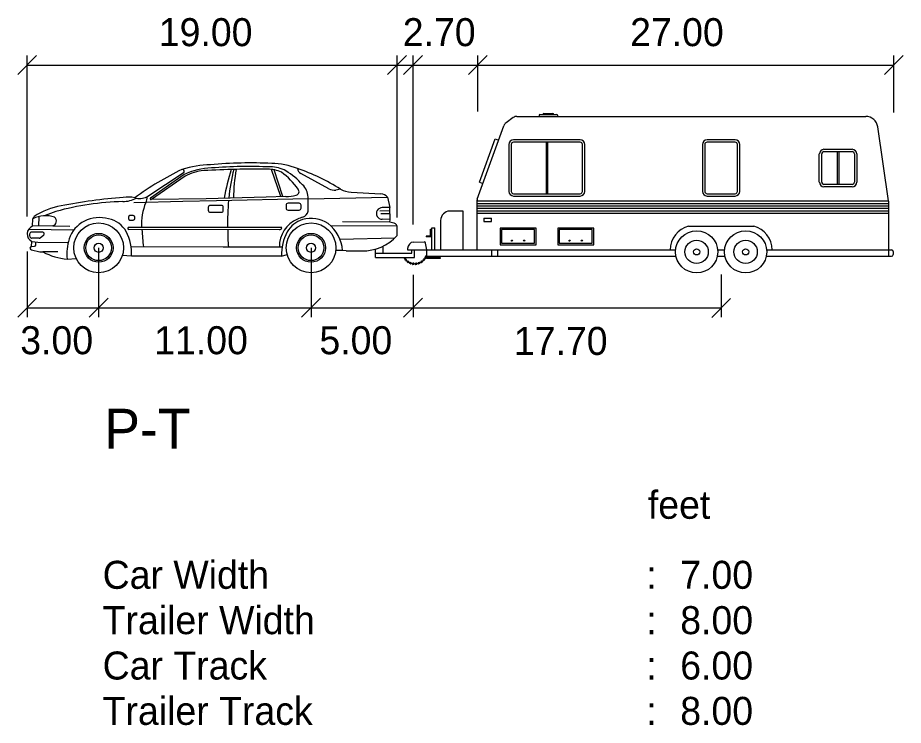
# Model space of a CAD drawing. Extents: x 2297881 to 2300600, y 559917 to 564426.
# Drawn here: x 2299107.93 to 2299149.45, y 562721.47 to 562754.62 of the extents above; entities that cross this region are included whole.
import ezdxf

# ---------------------------------------------------------------- set-up
doc = ezdxf.new("R2010")
doc.units = 0
doc.layers.add('DR_X_Elev_Flow', color=7, linetype='Continuous')

msp = doc.modelspace()

# ---------------------------------------------------------------- linework, layer by layer
at = {"layer": 'DR_X_Elev_Flow'}
for p, q in [((2299108.812, 562752.842), (2299107.926, 562751.957)), ((2299108.369, 562745.307), (2299108.369, 562752.842)), ((2299126.157, 562752.842), (2299125.271, 562751.957)), ((2299125.714, 562745.255), (2299125.714, 562752.842)), ((2299126.905, 562752.842), (2299126.019, 562751.957)), ((2299126.462, 562744.925), (2299126.462, 562752.842)), ((2299129.941, 562752.842), (2299129.055, 562751.957)), ((2299129.498, 562750.218), (2299129.498, 562752.842)), ((2299149.446, 562752.842), (2299148.561, 562751.957)), ((2299149.004, 562750.183), (2299149.004, 562752.842)), ((2299108.369, 562752.4), (2299149.004, 562752.4)), ((2299131.329, 562749.996), (2299147.683, 562749.996)), ((2299132.374, 562750.054), (2299132.374, 562749.996)), ((2299132.402, 562750.083), (2299133.207, 562750.083)), ((2299132.596, 562750.136), (2299133.013, 562750.136)), ((2299133.236, 562750.054), (2299133.236, 562749.996)), ((2299131.161, 562749.942), (2299130.821, 562749.696)), ((2299129.474, 562746.124), (2299130.716, 562749.553)), ((2299148.752, 562746.043), (2299148.252, 562749.504)), ((2299129.573, 562746.908), (2299130.311, 562748.945)), ((2299130.311, 562748.945), (2299130.474, 562748.886)), ((2299134.297, 562748.894), (2299131.174, 562748.894)), ((2299134.297, 562748.785), (2299131.174, 562748.785)), ((2299132.699, 562748.785), (2299132.699, 562746.374)), ((2299132.771, 562748.785), (2299132.771, 562746.374)), ((2299141.565, 562748.894), (2299140.249, 562748.894)), ((2299141.565, 562748.785), (2299140.249, 562748.785)), ((2299130.955, 562748.676), (2299130.955, 562746.483)), ((2299131.064, 562748.676), (2299131.064, 562746.483)), ((2299134.406, 562746.483), (2299134.406, 562748.676)), ((2299134.516, 562746.483), (2299134.516, 562748.676)), ((2299140.03, 562748.676), (2299140.03, 562746.483)), ((2299140.14, 562748.676), (2299140.14, 562746.483)), ((2299141.674, 562746.483), (2299141.674, 562748.676)), ((2299141.784, 562746.483), (2299141.784, 562748.676)), ((2299145.729, 562748.452), (2299147.045, 562748.452)), ((2299145.729, 562748.343), (2299147.045, 562748.343)), ((2299146.351, 562748.343), (2299146.351, 562746.808)), ((2299146.423, 562748.343), (2299146.423, 562746.808)), ((2299145.51, 562746.918), (2299145.51, 562748.234)), ((2299145.62, 562746.918), (2299145.62, 562748.234)), ((2299147.154, 562748.234), (2299147.154, 562746.918)), ((2299147.264, 562748.234), (2299147.264, 562746.918)), ((2299120.261, 562746.24), (2299119.831, 562747.51)), ((2299113.982, 562746.228), (2299115.732, 562747.378)), ((2299115.724, 562747.279), (2299114.155, 562746.167)), ((2299115.772, 562747.19), (2299114.192, 562746.1)), ((2299120.364, 562746.244), (2299119.945, 562747.492)), ((2299122.515, 562746.604), (2299121.198, 562747.32)), ((2299129.573, 562746.908), (2299129.737, 562746.849)), ((2299147.045, 562746.808), (2299145.729, 562746.808)), ((2299147.045, 562746.699), (2299145.729, 562746.699)), ((2299123.061, 562746.584), (2299122.843, 562746.543)), ((2299123.559, 562746.447), (2299124.951, 562746.359)), ((2299131.174, 562746.374), (2299134.297, 562746.374)), ((2299131.174, 562746.264), (2299134.297, 562746.264)), ((2299140.249, 562746.374), (2299141.565, 562746.374)), ((2299140.249, 562746.264), (2299141.565, 562746.264)), ((2299115.673, 562746.004), (2299113.363, 562745.949)), ((2299116.765, 562746.14), (2299114.177, 562746.1)), ((2299117.245, 562746.044), (2299115.673, 562746.004)), ((2299119.572, 562746.215), (2299116.765, 562746.14)), ((2299121.545, 562746.137), (2299117.245, 562746.044)), ((2299120.493, 562746.249), (2299119.572, 562746.215)), ((2299121.118, 562745.926), (2299120.599, 562745.926)), ((2299121.537, 562745.997), (2299121.544, 562746.215)), ((2299121.537, 562745.557), (2299121.537, 562745.997)), ((2299121.545, 562746.137), (2299125.265, 562746.218)), ((2299125.265, 562746.218), (2299125.38, 562745.732)), ((2299129.46, 562746.033), (2299148.753, 562746.033)), ((2299129.46, 562746.033), (2299129.46, 562743.739)), ((2299129.46, 562745.918), (2299148.753, 562745.918)), ((2299148.753, 562746.023), (2299148.753, 562743.447)), ((2299109.72, 562745.542), (2299109.212, 562745.344)), ((2299116.863, 562745.732), (2299116.863, 562745.595)), ((2299117.474, 562745.824), (2299116.955, 562745.824)), ((2299116.955, 562745.503), (2299117.474, 562745.503)), ((2299117.566, 562745.595), (2299117.566, 562745.732)), ((2299120.507, 562745.834), (2299120.507, 562745.698)), ((2299120.599, 562745.605), (2299121.118, 562745.605)), ((2299121.21, 562745.698), (2299121.21, 562745.834)), ((2299125.381, 562745.564), (2299124.908, 562745.561)), ((2299125.382, 562745.422), (2299124.947, 562745.425)), ((2299125.38, 562745.732), (2299125.02, 562745.719)), ((2299125.383, 562745.158), (2299125.38, 562745.732)), ((2299128.81, 562745.557), (2299128.187, 562745.557)), ((2299128.81, 562743.739), (2299128.81, 562745.557)), ((2299129.46, 562745.803), (2299148.753, 562745.803)), ((2299129.46, 562745.688), (2299148.753, 562745.688)), ((2299129.46, 562745.573), (2299148.753, 562745.573)), ((2299129.46, 562745.458), (2299148.753, 562745.458)), ((2299108.62, 562744.849), (2299108.634, 562745.199)), ((2299108.634, 562745.199), (2299108.698, 562745.299)), ((2299108.913, 562744.856), (2299108.938, 562745.311)), ((2299113.114, 562745.274), (2299113.114, 562745.21)), ((2299113.347, 562745.348), (2299113.188, 562745.348)), ((2299113.188, 562745.136), (2299113.347, 562745.136)), ((2299113.421, 562745.21), (2299113.421, 562745.274)), ((2299125.38, 562745.039), (2299123.154, 562745.049)), ((2299125.383, 562745.158), (2299125.017, 562745.174)), ((2299125.38, 562745.039), (2299125.383, 562745.158)), ((2299125.504, 562745.005), (2299125.38, 562745.039)), ((2299127.756, 562745.125), (2299127.756, 562743.739)), ((2299129.782, 562745.231), (2299130.135, 562745.231)), ((2299129.782, 562745.231), (2299129.782, 562745.073)), ((2299129.782, 562745.073), (2299130.135, 562745.073)), ((2299130.135, 562745.073), (2299130.135, 562745.231)), ((2299110.556, 562744.67), (2299108.427, 562744.69)), ((2299109.57, 562744.871), (2299108.62, 562744.849)), ((2299109.57, 562744.871), (2299110.37, 562744.849)), ((2299120.313, 562744.787), (2299113.104, 562744.79)), ((2299120.197, 562744.685), (2299113.139, 562744.693)), ((2299125.714, 562744.854), (2299122.612, 562744.868)), ((2299125.714, 562744.413), (2299125.714, 562744.854)), ((2299127.281, 562744.706), (2299127.337, 562744.706)), ((2299127.281, 562744.355), (2299127.281, 562744.706)), ((2299127.315, 562744.355), (2299127.315, 562744.706)), ((2299127.315, 562744.615), (2299127.337, 562744.615)), ((2299127.337, 562743.739), (2299127.337, 562744.771)), ((2299127.337, 562744.771), (2299127.48, 562744.771)), ((2299127.48, 562743.739), (2299127.48, 562744.771)), ((2299132.227, 562744.762), (2299130.54, 562744.762)), ((2299130.54, 562744.762), (2299130.54, 562743.978)), ((2299132.155, 562744.69), (2299130.611, 562744.69)), ((2299130.611, 562744.69), (2299130.611, 562744.05)), ((2299132.155, 562744.05), (2299132.155, 562744.69)), ((2299132.227, 562743.978), (2299132.227, 562744.762)), ((2299133.244, 562744.762), (2299133.244, 562743.978)), ((2299134.931, 562744.762), (2299133.244, 562744.762)), ((2299133.316, 562744.69), (2299133.316, 562744.05)), ((2299134.859, 562744.69), (2299133.316, 562744.69)), ((2299134.859, 562744.05), (2299134.859, 562744.69)), ((2299134.931, 562743.978), (2299134.931, 562744.762)), ((2299139.379, 562744.851), (2299142.435, 562744.851)), ((2299109.101, 562744.572), (2299108.575, 562744.572)), ((2299108.933, 562744.287), (2299108.59, 562744.287)), ((2299108.979, 562744.303), (2299109.148, 562744.442)), ((2299125.601, 562744.297), (2299123.031, 562744.231)), ((2299127.078, 562744.39), (2299127.078, 562744.355)), ((2299127.281, 562744.39), (2299127.078, 562744.39)), ((2299127.315, 562744.355), (2299127.078, 562744.355)), ((2299108.566, 562743.897), (2299108.583, 562744.14)), ((2299108.566, 562743.897), (2299108.709, 562743.912)), ((2299108.583, 562744.14), (2299108.873, 562744.097)), ((2299108.775, 562743.983), (2299108.779, 562744.111)), ((2299108.873, 562744.097), (2299110.259, 562744.09)), ((2299111.721, 562743.839), (2299111.721, 562740.59)), ((2299117.559, 562743.873), (2299113.244, 562743.882)), ((2299120.323, 562743.873), (2299117.559, 562743.873)), ((2299121.68, 562743.839), (2299121.68, 562740.59)), ((2299124.7, 562743.39), (2299124.7, 562743.778)), ((2299125.056, 562743.59), (2299125.056, 562743.915)), ((2299126.209, 562743.807), (2299126.209, 562743.739)), ((2299126.492, 562744.107), (2299126.979, 562744.122)), ((2299127.109, 562743.739), (2299127.052, 562744.062)), ((2299130.54, 562743.978), (2299132.227, 562743.978)), ((2299130.611, 562744.05), (2299132.155, 562744.05)), ((2299133.244, 562743.978), (2299134.931, 562743.978)), ((2299133.316, 562744.05), (2299134.859, 562744.05)), ((2299108.369, 562743.666), (2299108.369, 562740.59)), ((2299109.802, 562743.654), (2299109.109, 562743.647)), ((2299113.26, 562743.445), (2299112.83, 562743.48)), ((2299120.298, 562743.45), (2299113.26, 562743.445)), ((2299120.298, 562743.45), (2299120.558, 562743.523)), ((2299123.113, 562743.714), (2299122.839, 562743.717)), ((2299123.32, 562743.693), (2299123.113, 562743.714)), ((2299123.32, 562743.693), (2299124.06, 562743.693)), ((2299124.7, 562743.59), (2299126.399, 562743.59)), ((2299124.7, 562743.39), (2299126.525, 562743.39)), ((2299126.03, 562743.365), (2299126.015, 562743.39)), ((2299126.099, 562743.296), (2299126.057, 562743.37)), ((2299126.067, 562743.36), (2299126.061, 562743.356)), ((2299126.209, 562743.739), (2299138.521, 562743.739)), ((2299126.399, 562743.59), (2299126.399, 562743.739)), ((2299126.525, 562743.39), (2299126.525, 562743.739)), ((2299127.033, 562743.361), (2299126.981, 562743.294)), ((2299127.025, 562743.413), (2299127.009, 562743.377)), ((2299127.086, 562743.488), (2299127.052, 562743.41)), ((2299127.055, 562743.425), (2299127.061, 562743.422)), ((2299127.073, 562743.392), (2299127.058, 562743.356)), ((2299127.089, 562743.739), (2299127.089, 562743.447)), ((2299127.089, 562743.447), (2299130.42, 562743.447)), ((2299127.089, 562743.378), (2299127.089, 562743.343)), ((2299127.728, 562743.378), (2299127.089, 562743.378)), ((2299127.337, 562743.378), (2299127.337, 562743.447)), ((2299127.48, 562743.378), (2299127.48, 562743.447)), ((2299127.728, 562743.378), (2299127.728, 562743.343)), ((2299130.133, 562743.739), (2299130.133, 562743.447)), ((2299130.42, 562743.739), (2299130.42, 562743.447)), ((2299130.42, 562743.447), (2299138.79, 562743.447)), ((2299138.521, 562743.739), (2299138.774, 562743.739)), ((2299140.726, 562743.447), (2299141.088, 562743.447)), ((2299140.743, 562743.739), (2299141.072, 562743.739)), ((2299143.024, 562743.447), (2299148.753, 562743.447)), ((2299143.041, 562743.739), (2299143.293, 562743.739)), ((2299143.293, 562743.739), (2299148.9, 562743.739)), ((2299148.753, 562743.447), (2299148.9, 562743.447)), ((2299148.972, 562743.667), (2299148.972, 562743.519)), ((2299110.246, 562743.307), (2299110.669, 562743.337)), ((2299126.112, 562743.248), (2299126.085, 562743.276)), ((2299126.09, 562743.313), (2299126.086, 562743.309)), ((2299126.15, 562743.284), (2299126.123, 562743.313)), ((2299126.196, 562743.198), (2299126.137, 562743.26)), ((2299126.149, 562743.252), (2299126.144, 562743.247)), ((2299126.184, 562743.213), (2299126.18, 562743.207)), ((2299126.22, 562743.154), (2299126.187, 562743.175)), ((2299126.249, 562743.199), (2299126.215, 562743.22)), ((2299126.314, 562743.127), (2299126.242, 562743.172)), ((2299126.256, 562743.167), (2299126.252, 562743.161)), ((2299126.298, 562743.137), (2299126.296, 562743.131)), ((2299126.348, 562743.09), (2299126.311, 562743.102)), ((2299126.365, 562743.14), (2299126.327, 562743.152)), ((2299126.446, 562743.086), (2299126.365, 562743.112)), ((2299126.379, 562743.111), (2299126.377, 562743.105)), ((2299126.428, 562743.093), (2299126.428, 562743.086)), ((2299126.488, 562743.059), (2299126.449, 562743.061)), ((2299126.492, 562743.111), (2299126.453, 562743.114)), ((2299126.583, 562743.078), (2299126.498, 562743.084)), ((2299126.513, 562743.087), (2299126.513, 562743.08)), ((2299126.565, 562743.081), (2299126.566, 562743.074)), ((2299126.622, 562743.114), (2299126.583, 562743.107)), ((2299126.631, 562743.062), (2299126.593, 562743.055)), ((2299126.719, 562743.105), (2299126.635, 562743.09)), ((2299126.649, 562743.096), (2299126.65, 562743.089)), ((2299126.7, 562743.102), (2299126.703, 562743.096)), ((2299126.748, 562743.149), (2299126.712, 562743.133)), ((2299126.769, 562743.101), (2299126.733, 562743.085)), ((2299126.844, 562743.163), (2299126.766, 562743.128)), ((2299126.778, 562743.137), (2299126.781, 562743.131)), ((2299126.826, 562743.156), (2299126.83, 562743.151)), ((2299126.861, 562743.213), (2299126.83, 562743.189)), ((2299126.894, 562743.172), (2299126.863, 562743.147)), ((2299126.951, 562743.25), (2299126.884, 562743.198)), ((2299126.893, 562743.209), (2299126.897, 562743.204)), ((2299126.955, 562743.303), (2299126.931, 562743.272)), ((2299126.935, 562743.24), (2299126.941, 562743.235)), ((2299126.997, 562743.271), (2299126.973, 562743.24)), ((2299126.987, 562743.307), (2299126.993, 562743.303)), ((2299127.021, 562743.347), (2299127.027, 562743.344)), ((2299127.728, 562743.343), (2299127.089, 562743.343)), ((2299126.462, 562742.57), (2299126.462, 562740.59)), ((2299140.907, 562742.592), (2299140.907, 562740.59)), ((2299108.812, 562741.476), (2299107.926, 562740.59)), ((2299112.164, 562741.476), (2299111.278, 562740.59)), ((2299122.123, 562741.476), (2299121.237, 562740.59)), ((2299126.905, 562741.476), (2299126.019, 562740.59)), ((2299141.35, 562741.459), (2299140.464, 562740.573)), ((2299108.369, 562741.033), (2299140.907, 562741.033))]:
    msp.add_line(p, q, dxfattribs=at)
for centre, radius in [((2299111.721, 562743.839), 1.166), ((2299121.68, 562743.839), 1.166), ((2299139.758, 562743.648), 0.989), ((2299142.056, 562743.648), 0.989), ((2299111.721, 562743.839), 0.677), ((2299111.721, 562743.839), 0.603), ((2299121.68, 562743.839), 0.677), ((2299121.68, 562743.839), 0.603), ((2299131.096, 562744.174), 0.0256), ((2299131.67, 562744.174), 0.0256), ((2299133.8, 562744.174), 0.0256), ((2299134.375, 562744.174), 0.0256), ((2299139.758, 562743.648), 0.547), ((2299142.056, 562743.648), 0.547), ((2299111.719, 562743.839), 0.214), ((2299121.678, 562743.839), 0.214), ((2299139.758, 562743.648), 0.144), ((2299142.056, 562743.648), 0.144)]:
    msp.add_circle(centre, radius, dxfattribs=at)
for centre, radius, start, end in [((2299131.329, 562749.709), 0.287, 90, 125.8387), ((2299132.402, 562750.054), 0.0287, 90, 180), ((2299132.609, 562750.081), 0.0567, 103.353, 178.0683), ((2299133, 562750.081), 0.0567, 1.9317, 76.647), ((2299133.207, 562750.054), 0.0287, 0, 90), ((2299147.683, 562749.421), 0.575, 8.2273, 90), ((2299130.989, 562749.463), 0.287, 125.8387, 161.6774), ((2299131.174, 562748.676), 0.218, 90, 180), ((2299131.174, 562748.676), 0.109, 90, 180), ((2299134.297, 562748.676), 0.218, 360, 90), ((2299134.297, 562748.676), 0.109, 360, 90), ((2299140.249, 562748.676), 0.218, 90, 180), ((2299140.249, 562748.676), 0.109, 90, 180), ((2299141.565, 562748.676), 0.218, 360, 90), ((2299141.565, 562748.676), 0.109, 360, 90), ((2299145.729, 562748.234), 0.218, 90, 180), ((2299145.729, 562748.234), 0.109, 90, 180), ((2299147.045, 562748.234), 0.218, 360, 90), ((2299147.045, 562748.234), 0.109, 360, 90), ((2299122.201, 562734.033), 14.995, 115.9971, 125.8595), ((2299117.126, 562742.542), 5.189, 91.7728, 106.767), ((2299115.641, 562747.413), 0.098, 338.7512, 97.138), ((2299117.129, 562744.166), 3.414, 92.0559, 114.2845), ((2299119.064, 562702.476), 45.045, 89.2591, 93.0743), ((2299118.855, 562726.648), 21.165, 87.3513, 95.1236), ((2299118.785, 562724.592), 23.056, 87.553, 94.4258), ((2299127.218, 562744.588), 9.735, 162.5527, 170.6899), ((2299125.966, 562745.415), 8.179, 165.1593, 174.7143), ((2299124.261, 562746.251), 6.214, 168.2882, 180.7049), ((2299119.686, 562746.184), 1.334, 63.154, 91.6788), ((2299119.786, 562746.151), 1.476, 61.0673, 90.63), ((2299119.814, 562744.515), 3.275, 67.9907, 89.6559), ((2299118.013, 562738.644), 9.408, 57.553, 71.2258), ((2299121.302, 562747.559), 0.261, 181.6185, 246.5782), ((2299116.798, 562745.39), 2.072, 94.1205, 119.6618), ((2299118.523, 562744.837), 3.091, 34.3906, 55.159), ((2299118.666, 562744.449), 3.51, 41.9269, 58.5069), ((2299120.668, 562746.164), 0.877, 3.3428, 45.9853), ((2299145.729, 562746.918), 0.218, 180, 270), ((2299145.729, 562746.918), 0.109, 180, 270), ((2299147.045, 562746.918), 0.218, 270, 0), ((2299147.045, 562746.918), 0.109, 270, 0), ((2299120.575, 562747.747), 1.5, 266.8503, 285.8201), ((2299120.944, 562746.47), 0.171, 283.5223, 41.2666), ((2299122.791, 562747.174), 0.634, 244.1451, 274.6321), ((2299123.596, 562747.561), 1.114, 241.2884, 268.0918), ((2299124.958, 562745.955), 0.404, 40.5709, 90.998), ((2299131.174, 562746.483), 0.218, 180, 270), ((2299131.174, 562746.483), 0.109, 180, 270), ((2299134.297, 562746.483), 0.218, 270, 0), ((2299134.297, 562746.483), 0.109, 270, 0), ((2299140.249, 562746.483), 0.218, 180, 270), ((2299140.249, 562746.483), 0.109, 180, 270), ((2299141.565, 562746.483), 0.109, 270, 0), ((2299141.565, 562746.483), 0.218, 270, 0), ((2299113.23, 562732.654), 13.358, 91.634, 105.2352), ((2299115.018, 562719.291), 26.993, 94.5482, 100.7946), ((2299112.842, 562747.436), 1.43, 270.2883, 297.1222), ((2299113.11, 562744.649), 1.567, 78.6761, 98.514), ((2299113.651, 562746.845), 0.7, 250.4981, 298.1814), ((2299116.518, 562744.918), 2.79, 158.0053, 182.6323), ((2299113.687, 562746.146), 0.306, 323.1539, 15.5477), ((2299114.176, 562746.137), 0.0368, 125.3064, 270.8889), ((2299131.873, 562744.889), 14.111, 175.2533, 180.4142), ((2299120.599, 562745.834), 0.0921, 90, 180), ((2299121.118, 562745.834), 0.0921, 0, 90), ((2299129.747, 562746.033), 0.287, 161.6774, 180), ((2299148.466, 562746.023), 0.287, 0, 3.965), ((2299110.553, 562742.504), 3.355, 100.1254, 123.5574), ((2299116.955, 562745.732), 0.0921, 90, 180), ((2299116.955, 562745.595), 0.0921, 180, 270), ((2299117.474, 562745.732), 0.0921, 0, 90), ((2299117.474, 562745.595), 0.0921, 270, 0), ((2299120.599, 562745.698), 0.0921, 180, 270), ((2299121.118, 562745.698), 0.0921, 270, 0), ((2299121.156, 562745.626), 0.387, 292.0027, 349.7344), ((2299125.017, 562745.447), 0.272, 89.4303, 269.8747), ((2299128.187, 562745.125), 0.431, 90, 180), ((2299109.228, 562744.056), 1.288, 70.5762, 117.4353), ((2299109.513, 562745.092), 0.229, 284.4681, 51.3236), ((2299111.665, 562743.85), 1.38, 116.4084, 163.0738), ((2299111.768, 562743.629), 1.623, 74.9346, 116.1868), ((2299111.961, 562744.019), 1.2, 28.748, 78.9995), ((2299113.188, 562745.274), 0.0736, 90, 180), ((2299113.188, 562745.21), 0.0736, 180, 270), ((2299113.347, 562745.274), 0.0736, 0, 90), ((2299113.347, 562745.21), 0.0736, 270, 360), ((2299121.555, 562743.92), 1.357, 112.0964, 181.968), ((2299121.669, 562743.931), 1.288, 107.4038, 149.7131), ((2299121.458, 562744.414), 0.869, 100.4094, 118.442), ((2299121.683, 562743.692), 1.521, 58.1254, 105.2223), ((2299108.758, 562744.486), 0.388, 110.8051, 243.2128), ((2299111.117, 562743.587), 2.147, 356.206, 28.0052), ((2299113.144, 562744.75), 0.0565, 134.529, 265.0873), ((2299140.485, 562746.692), 26.813, 184.2757, 186.017), ((2299124.377, 562744.501), 6.604, 178.4036, 185.4503), ((2299120.196, 562744.803), 0.118, 270.588, 352.214), ((2299121.231, 562743.503), 1.941, 6.084, 49.7223), ((2299125.52, 562744.806), 0.2, 13.7409, 94.6068), ((2299139.668, 562743.741), 1.147, 104.5901, 180.0878), ((2299142.146, 562743.741), 1.147, 359.9122, 75.4099), ((2299108.653, 562744.437), 0.173, 142.0596, 230.7171), ((2299108.575, 562744.499), 0.0736, 90, 142.0596), ((2299108.59, 562744.36), 0.0736, 230.7171, 270), ((2299108.933, 562744.36), 0.0736, 270, 309.3904), ((2299109.101, 562744.499), 0.0736, 309.3904, 90), ((2299112.28, 562743.571), 2.051, 160.6152, 187.3941), ((2299122.556, 562743.529), 2.26, 152.2555, 181.9987), ((2299124.096, 562745.869), 2.176, 269.0541, 318.0341), ((2299108.576, 562743.822), 0.0757, 98.0854, 261.9146), ((2299108.701, 562743.985), 0.0736, 275.9015, 358.1206), ((2299126.501, 562743.815), 0.292, 91.7027, 181.7027), ((2299126.981, 562744.05), 0.0718, 9.9916, 91.7027), ((2299109.125, 562745.262), 1.615, 249.7289, 269.4125), ((2299110.471, 562746.129), 2.831, 241.2322, 265.4466), ((2299126.05, 562743.376), 0.023, 209.6243, 299.6243), ((2299126.055, 562743.38), 0.023, 299.6243, 27.9874), ((2299127.03, 562743.368), 0.023, 156.4425, 246.4425), ((2299127.046, 562743.404), 0.023, 66.4425, 156.4425), ((2299127.036, 562743.365), 0.023, 246.4425, 336.4425), ((2299127.052, 562743.401), 0.023, 336.4425, 66.4425), ((2299148.9, 562743.667), 0.0719, 0, 90), ((2299148.9, 562743.519), 0.0719, 270, 0), ((2299126.101, 562743.292), 0.023, 133.7152, 223.7152), ((2299126.106, 562743.297), 0.023, 43.7152, 133.7152), ((2299126.129, 562743.264), 0.023, 223.7152, 313.7152), ((2299126.134, 562743.268), 0.023, 313.7152, 43.7152), ((2299126.199, 562743.195), 0.023, 147.8062, 237.8062), ((2299126.203, 562743.2), 0.023, 57.8062, 147.8062), ((2299126.233, 562743.174), 0.023, 237.8062, 327.8062), ((2299126.236, 562743.179), 0.023, 327.8062, 57.8062), ((2299126.318, 562743.124), 0.023, 161.8971, 251.8971), ((2299126.32, 562743.13), 0.023, 71.8971, 161.8971), ((2299126.355, 562743.112), 0.023, 251.8971, 341.8971), ((2299126.358, 562743.118), 0.023, 341.8971, 71.8971), ((2299126.451, 562743.091), 0.023, 85.988, 175.988), ((2299126.451, 562743.084), 0.023, 175.988, 265.988), ((2299126.49, 562743.082), 0.023, 265.988, 355.988), ((2299126.49, 562743.088), 0.023, 355.988, 85.988), ((2299126.587, 562743.085), 0.023, 100.0789, 190.0789), ((2299126.589, 562743.078), 0.023, 190.0789, 280.0789), ((2299126.626, 562743.092), 0.023, 10.0789, 100.0789), ((2299126.627, 562743.085), 0.023, 280.0789, 10.0789), ((2299126.721, 562743.112), 0.023, 114.1698, 204.1698), ((2299126.724, 562743.106), 0.023, 204.1698, 294.1698), ((2299126.757, 562743.128), 0.023, 24.1698, 114.1698), ((2299126.76, 562743.122), 0.023, 294.1698, 24.1698), ((2299126.844, 562743.171), 0.023, 128.2607, 218.2607), ((2299126.849, 562743.165), 0.023, 218.2607, 308.2607), ((2299126.875, 562743.195), 0.023, 38.2607, 128.2607), ((2299126.879, 562743.19), 0.023, 308.2607, 38.2607), ((2299126.949, 562743.258), 0.023, 142.3516, 232.3516), ((2299126.955, 562743.254), 0.023, 232.3516, 322.3516), ((2299126.973, 562743.289), 0.023, 52.3516, 142.3516), ((2299126.979, 562743.285), 0.023, 322.3516, 52.3516)]:
    msp.add_arc(centre, radius, start, end, dxfattribs=at)

# ---------------------------------------------------------------- texts
for s, height, p in [('19.00', 1.3123, (2299114.542, 562753.285)), ('2.70', 1.3123, (2299125.98, 562753.285)), ('27.00', 1.3123, (2299136.638, 562753.285)), ('3.00', 1.3123, (2299108.046, 562738.852)), ('11.00', 1.3123, (2299114.326, 562738.852)), ('5.00', 1.3123, (2299122.071, 562738.852)), ('17.70', 1.3123, (2299131.19, 562738.818)), ('P-T', 1.8748, (2299111.988, 562734.423)), ('feet', 1.3123, (2299137.472, 562731.142)), ('Car Width', 1.3123, (2299111.909, 562727.862)), (':', 1.312, (2299137.394, 562727.862)), ('7.00', 1.3123, (2299138.989, 562727.862)), ('Trailer Width', 1.31234, (2299111.909, 562725.737)), (':', 1.312, (2299137.394, 562725.737)), ('8.00', 1.3123, (2299138.989, 562725.737)), ('Car Track', 1.3123, (2299111.909, 562723.612)), ('6.00', 1.3123, (2299138.989, 562723.612)), (':', 1.312, (2299137.394, 562723.612)), ('Trailer Track', 1.31234, (2299111.909, 562721.487)), ('8.00', 1.3123, (2299138.989, 562721.487)), (':', 1.312, (2299137.394, 562721.487))]:
    msp.add_text(s, height=height, dxfattribs=at).set_placement(p)

doc.saveas('drawing.dxf')
